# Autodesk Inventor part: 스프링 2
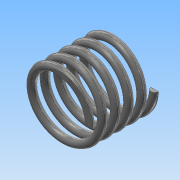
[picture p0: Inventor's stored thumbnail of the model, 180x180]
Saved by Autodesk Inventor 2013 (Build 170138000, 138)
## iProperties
Created: 2016-03
Part Number: 스프링 2
Material: 스테인리스강
Document SubType Name: Modeling
Designer: Administrator
Density: 8.08 g/cm^3
Mass: 6.61414 g
Surface Area: 16.6835 cm^2
Volume: 0.818581 cm^3
Author: Administrator
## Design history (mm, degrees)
sketch "스케치1"
  geometry: L1 (0, 0)-(8.5, 0); L2 (8.5, 17.5)-(0, 17.5); L3 (0, 17.5)-(0, 0); C1 r 1 at (8.5, 0)
  constraints: 6 end point, 2 parallel, 1 centre point, 1 coincident, 1 horizontal, 1 perpendicular
  dimensions: "d0" = 2 diameter of C1; "d1" = 17 diameter of C1.centre L3; "d2" = 17.5 distance between parallel lines of L1 L2 (derived)
feature "코일1" sketch "스케치1" pitch "d3" = 10; turns "d5" = 5; dims "d4" = 17.5 (= d2), "d6" = 0, angle "d7" = 90 deg, angle "d8" = 90 deg, "d9" = 0, "d10" = 0
sketch "스케치2"
  geometry: L1 (0, -15)-(17.5, -15); L2 (17.5, -15)-(17.5, 15); L3 (17.5, 15)-(0, 15); L4 (0, 15)-(0, -15); 2 further points
  constraints: 8 end point, 2 parallel, 1 coincident, 1 horizontal, 1 midpoint, 1 perpendicular
  dimensions: "d11" = 17.5 distance between parallel lines of L4 L2 (derived); "d13" = 30 distance of L1.end L2.end
extrude "돌출1" sketch "스케치2" stored distance "d14" = 0; taper "d15" = 0 deg
node "솔리드1"
